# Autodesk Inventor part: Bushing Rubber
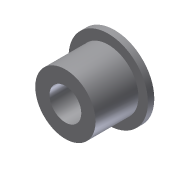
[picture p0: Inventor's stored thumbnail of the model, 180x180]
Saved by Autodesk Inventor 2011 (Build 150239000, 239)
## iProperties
Created: 2010-03
Part Number: Bushing Rubber
Document SubType Name: Modeling
Designer: bhakira
Density: 1 g/cm^3
Author: bhakira
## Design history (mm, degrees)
sketch "Sketch1"
  geometry: L1 (25, 31)-(25, 27); L2 (25, 27)-(19, 27); L3 (19, 27)-(19, 0); L4 (19, 0)-(0, 0); L5 (0, 0)-(0, 31); L6 (0, 31)-(25, 31); 1 further point
  constraints: 12 end point, 1 coincident, 1 other
  dimensions: "d1" = 50 diameter of L1 L5; "d2" = 38 diameter of L3 L5; "d3" = 4 distance of L1.start L1.end; "d4" = 27 distance between parallel lines of L4 L2
revolve "Revolution1" sketch "Sketch1" stored, may be unused: angle "d5" = 90 deg
hole "Hole1" diameter "d8" = 20; stored, may be unused: countersink angle "d12" = 82 deg, drill point angle "d14" = 118 deg; dims "d6" = 10, "d7" = 10, "d9" = 6, "d10" = 34.925, "d11" = 2, "d13" = 8
body "Solid1"
